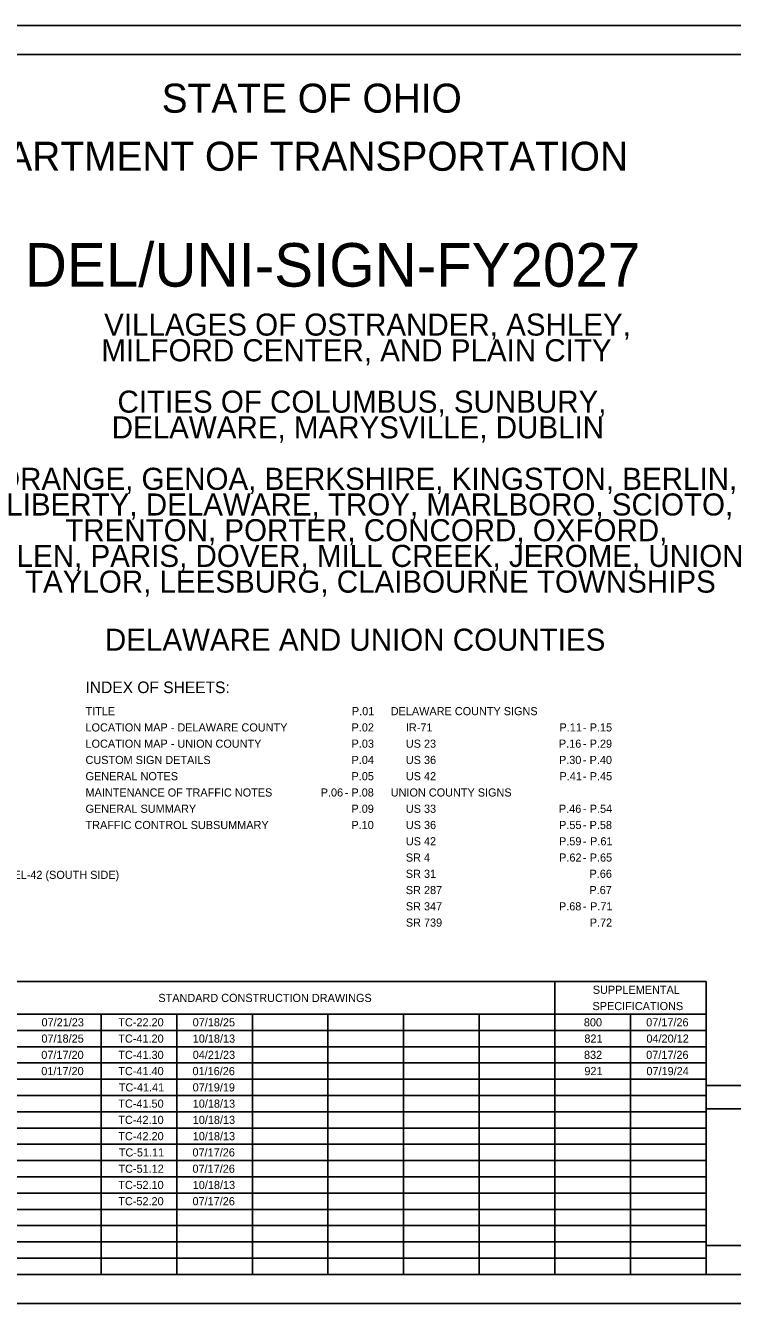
# Model space of a CAD drawing. Extents: x 0 to 34, y 0 to 22.
# Drawn here: x 11.45 to 23.62, y 0 to 22 of the extents above; entities that cross this region are included whole.
import ezdxf

# ---------------------------------------------------------------- set-up
doc = ezdxf.new("R2010")
doc.units = 0
for name, color, linetype in [('SH_Border', 7, 'Continuous'), ('SH_Cut_Line', 7, 'Continuous'), ('SH_Data', 7, 'Continuous'), ('SH_Text', 7, 'Continuous')]:
    doc.layers.add(name, color=color, linetype=linetype)

msp = doc.modelspace()

# ---------------------------------------------------------------- linework, layer by layer
at = {"layer": 'SH_Border'}
msp.add_lwpolyline([(1.5, 21.5), (33.5, 21.5), (33.5, 0.5), (1.5, 0.5)], close=True, dxfattribs=at)
at = {"layer": 'SH_Cut_Line'}
msp.add_lwpolyline([(0, 0), (34, 0), (34, 22), (0, 22)], close=True, dxfattribs=at)
at = {"layer": 'SH_Data'}
for p, q in [((10.15, 5.54), (23.162, 5.54)), ((20.559, 5.54), (20.559, 0.5)), ((23.162, 5.54), (23.162, 0.5)), ((10.15, 4.98), (23.162, 4.98)), ((12.752, 4.98), (12.752, 0.5)), ((14.054, 4.98), (14.054, 0.5)), ((15.355, 4.98), (15.355, 0.5)), ((16.656, 4.98), (16.656, 0.5)), ((17.957, 4.98), (17.957, 0.5)), ((19.258, 4.98), (19.258, 0.5)), ((21.861, 4.98), (21.861, 0.5)), ((10.15, 4.7), (23.162, 4.7)), ((10.15, 4.42), (23.162, 4.42)), ((10.15, 4.14), (23.162, 4.14)), ((10.15, 3.86), (23.162, 3.86)), ((23.162, 0.5), (23.162, 3.75)), ((23.162, 3.75), (25.962, 3.75)), ((10.15, 3.58), (23.162, 3.58)), ((10.15, 3.3), (23.162, 3.3)), ((23.162, 3.35), (25.962, 3.35)), ((10.15, 3.02), (23.162, 3.02)), ((10.15, 2.74), (23.162, 2.74)), ((10.15, 2.46), (23.162, 2.46)), ((10.15, 2.18), (23.162, 2.18)), ((10.15, 1.9), (23.162, 1.9)), ((10.15, 1.62), (23.162, 1.62)), ((10.15, 1.34), (23.162, 1.34)), ((10.15, 1.06), (23.162, 1.06)), ((10.15, 0.78), (23.162, 0.78)), ((10.15, 0.5), (23.162, 0.5)), ((23.162, 0.5), (25.962, 0.5))]:
    msp.add_line(p, q, dxfattribs=at)
msp.add_lwpolyline([(23.162, 0.5), (23.162, 1), (25.962, 1), (25.962, 0.5)], close=True, dxfattribs=at)

# ---------------------------------------------------------------- texts
at = {"layer": 'SH_Text'}
for s, height, p in [('STATE OF OHIO', 0.5, (13.795, 20.5)), ('DEPARTMENT OF TRANSPORTATION', 0.5, (9.747, 19.5)), ('DEL/UNI-SIGN-FY2027', 0.75, (11.44, 17.505)), ('VILLAGES OF OSTRANDER, ASHLEY,', 0.38, (12.804, 16.662)), ('MILFORD CENTER, AND PLAIN CITY', 0.38, (12.756, 16.22)), ('CITIES OF COLUMBUS, SUNBURY,', 0.38, (13.034, 15.335)), ('DELAWARE, MARYSVILLE, DUBLIN', 0.38, (12.935, 14.892)), ('ORANGE, GENOA, BERKSHIRE, KINGSTON, BERLIN,', 0.38, (10.963, 14.007)), ('LIBERTY, DELAWARE, TROY, MARLBORO, SCIOTO,', 0.38, (11.121, 13.565)), ('TRENTON, PORTER, CONCORD, OXFORD,', 0.38, (12.135, 13.122)), ('ALLEN, PARIS, DOVER, MILL CREEK, JEROME, UNION,', 0.38, (10.677, 12.68)), ('TAYLOR, LEESBURG, CLAIBOURNE TOWNSHIPS', 0.38, (11.442, 12.237)), ('DELAWARE AND UNION COUNTIES', 0.38, (12.818, 11.237)), ('INDEX OF SHEETS:', 0.2, (12.484, 10.507)), ('TITLE', 0.14, (12.484, 10.127)), ('P.01', 0.14, (17.068, 10.127)), ('DELAWARE COUNTY SIGNS', 0.14, (17.736, 10.127)), ('LOCATION MAP - DELAWARE COUNTY', 0.14, (12.484, 9.847)), ('P.02', 0.14, (17.062, 9.847)), ('     IR-71', 0.14, (17.736, 9.847)), ('P.11', 0.14, (20.64, 9.847)), ('-', 0.14, (21.044, 9.847)), ('P.15', 0.14, (21.16, 9.847)), ('LOCATION MAP - UNION COUNTY', 0.14, (12.484, 9.567)), ('P.03', 0.14, (17.062, 9.567)), ('     US 23', 0.14, (17.736, 9.567)), ('P.16', 0.14, (20.63, 9.567)), ('P.29', 0.14, (21.159, 9.567)), ('-', 0.14, (21.044, 9.567)), ('CUSTOM SIGN DETAILS', 0.14, (12.484, 9.287)), ('P.04', 0.14, (17.062, 9.287)), ('     US 36', 0.14, (17.736, 9.287)), ('P.30', 0.14, (20.631, 9.287)), ('-', 0.14, (21.044, 9.287)), ('P.40', 0.14, (21.158, 9.287)), ('GENERAL NOTES', 0.14, (12.484, 9.007)), ('P.05', 0.14, (17.061, 9.007)), ('     US 42', 0.14, (17.736, 9.007)), ('P.41', 0.14, (20.64, 9.007)), ('-', 0.14, (21.044, 9.007)), ('P.45', 0.14, (21.16, 9.007)), ('MAINTENANCE OF TRAFFIC NOTES', 0.14, (12.484, 8.727)), ('P.06', 0.14, (16.531, 8.727)), ('P.08', 0.14, (17.06, 8.727)), ('UNION COUNTY SIGNS', 0.14, (17.736, 8.727)), ('GENERAL SUMMARY', 0.14, (12.484, 8.447)), ('-', 0.14, (16.945, 8.727)), ('P.09', 0.14, (17.06, 8.447)), ('     US 33', 0.14, (17.736, 8.447)), ('P.46', 0.14, (20.63, 8.447)), ('P.54', 0.14, (21.161, 8.447)), ('-', 0.14, (21.044, 8.447)), ('TRAFFIC CONTROL SUBSUMMARY', 0.14, (12.484, 8.167)), ('P.10', 0.14, (17.059, 8.167)), ('     US 36', 0.14, (17.736, 8.167)), ('P.55', 0.14, (20.633, 8.167)), ('-', 0.14, (21.044, 8.167)), ('P.58', 0.14, (21.158, 8.167)), ('     US 42', 0.14, (17.736, 7.887)), ('P.59', 0.14, (20.632, 7.887)), ('-', 0.14, (21.044, 7.887)), ('P.61', 0.14, (21.167, 7.887)), ('     SR 4', 0.14, (17.736, 7.607)), ('P.62', 0.14, (20.634, 7.607)), ('P.65', 0.14, (21.16, 7.607)), ('-', 0.14, (21.044, 7.607)), ('DEL-71, DEL-23, DEL-36 (EAST SIDE), DEL-42 (SOUTH SIDE)', 0.14, (7.737, 7.309)), ('     SR 31', 0.14, (17.736, 7.327)), ('P.66', 0.14, (21.157, 7.327)), ('     SR 287', 0.14, (17.736, 7.047)), ('P.67', 0.14, (21.155, 7.047)), ('     SR 347', 0.14, (17.736, 6.767)), ('P.68', 0.14, (20.631, 6.767)), ('-', 0.14, (21.044, 6.767)), ('P.71', 0.14, (21.167, 6.767)), ('     SR 739', 0.14, (17.736, 6.487)), ('P.72', 0.14, (21.161, 6.487)), ('STANDARD CONSTRUCTION DRAWINGS', 0.14, (13.737, 5.19)), ('SUPPLEMENTAL', 0.14, (21.213, 5.33)), ('SPECIFICATIONS', 0.14, (21.208, 5.05)), ('07/21/23', 0.14, (11.727, 4.77)), ('TC-22.20', 0.14, (13.048, 4.77)), ('07/18/25', 0.14, (14.328, 4.77)), ('800', 0.14, (21.059, 4.77)), ('07/17/26', 0.14, (22.132, 4.77)), ('07/18/25', 0.14, (11.725, 4.49)), ('TC-41.20', 0.14, (13.048, 4.49)), ('10/18/13', 0.14, (14.329, 4.49)), ('821', 0.14, (21.068, 4.49)), ('04/20/12', 0.14, (22.136, 4.49)), ('07/17/20', 0.14, (11.723, 4.21)), ('TC-41.30', 0.14, (13.048, 4.21)), ('04/21/23', 0.14, (14.329, 4.21)), ('832', 0.14, (21.062, 4.21)), ('07/17/26', 0.14, (22.132, 4.21)), ('01/17/20', 0.14, (11.723, 3.93)), ('TC-41.40', 0.14, (13.048, 3.93)), ('01/16/26', 0.14, (14.325, 3.93)), ('921', 0.14, (21.068, 3.93)), ('07/19/24', 0.14, (22.136, 3.93)), ('TC-41.41', 0.14, (13.057, 3.65)), ('07/19/19', 0.14, (14.327, 3.65)), ('TC-41.50', 0.14, (13.048, 3.37)), ('10/18/13', 0.14, (14.329, 3.37)), ('TC-42.10', 0.14, (13.048, 3.09)), ('10/18/13', 0.14, (14.329, 3.09)), ('TC-42.20', 0.14, (13.048, 2.81)), ('10/18/13', 0.14, (14.329, 2.81)), ('TC-51.11', 0.14, (13.057, 2.53)), ('07/17/26', 0.14, (14.325, 2.53)), ('TC-51.12', 0.14, (13.051, 2.25)), ('07/17/26', 0.14, (14.325, 2.25)), ('TC-52.10', 0.14, (13.048, 1.97)), ('10/18/13', 0.14, (14.329, 1.97)), ('TC-52.20', 0.14, (13.048, 1.69)), ('07/17/26', 0.14, (14.325, 1.69))]:
    msp.add_text(s, height=height, dxfattribs=at).set_placement(p)

doc.saveas('drawing.dxf')
